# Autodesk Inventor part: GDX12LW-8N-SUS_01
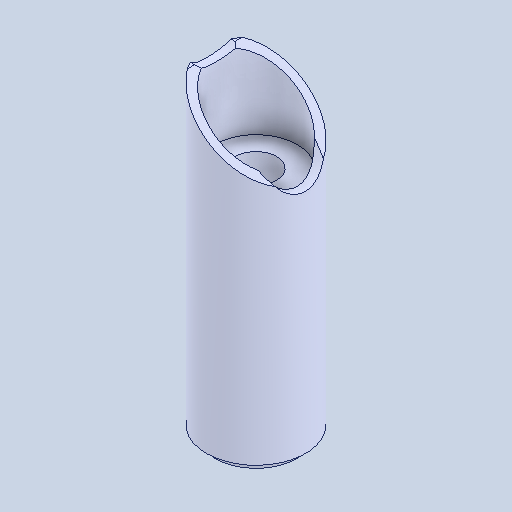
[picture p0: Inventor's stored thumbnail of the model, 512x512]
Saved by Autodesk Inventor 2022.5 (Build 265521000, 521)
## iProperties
Created: 2024-06
Part Number: GDX12LW-8N-SUS_01
Material: 一般
Document SubType Name: Modeling
Designer: ImaoCorp
Density: 1 g/cm^3
Appearance: 既定
Author: ImaoCorp
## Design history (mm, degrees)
feature "GDX12LW-8N-SUS_01"
node "ソリッド1"
